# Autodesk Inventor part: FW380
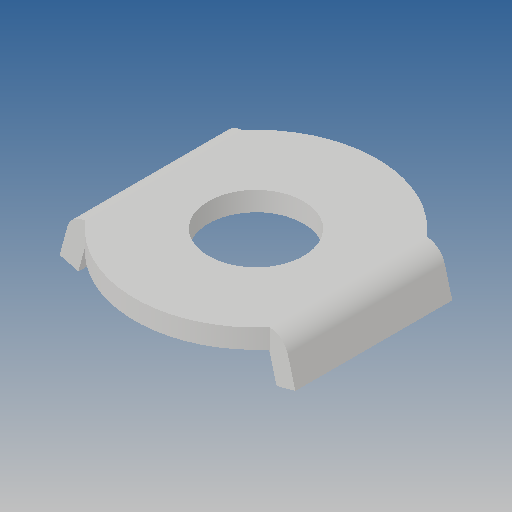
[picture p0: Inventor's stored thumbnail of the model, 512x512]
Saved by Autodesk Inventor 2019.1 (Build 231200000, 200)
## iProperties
Created: 2011-05
Part Number: FW380
Material: Ogólny
Document SubType Name: Modeling
Designer: CADENGINEERING4
Density: 1 g/cm^3
Appearance: Domyślna
Author: CADENGINEERING4
Revision Number: ÈÎºÎ
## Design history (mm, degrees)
feature "ÇÐ³ý-À­Éì1"
node "Bryła1"
